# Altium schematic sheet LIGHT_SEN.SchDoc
size A4; Revision: V1.2; SheetNumber: 6; SheetTotal: 10
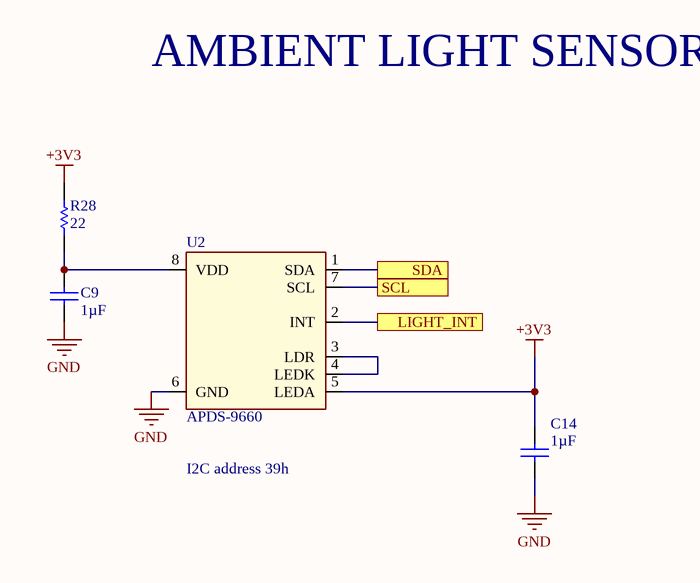
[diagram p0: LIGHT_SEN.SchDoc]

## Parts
C9  value 1µF  [CAP-0402]  (hidden comment: C0402C105K8PACTU)
C14  value 1µF  [CAP-0402]  (hidden comment: C0402C105K8PACTU)
R28  value 22  [RES-0402]  (hidden comment: RC0402FR-0722RL)
U2  APDS-9660  [APDS-9660-Footprint-1]

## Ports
LIGHT_INT, SCL, SDA

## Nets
+3V3: C14.1 R28.2 U2.5(LEDA)
GND: C9.1 C14.2 U2.6(GND)
LIGHT_INT: U2.2(INT) ; port LIGHT_INT
SCL: U2.7(SCL) ; port SCL
SDA: U2.1(SDA) ; port SDA
NetC9_2: C9.2 R28.1 U2.8(VDD)
NetU2_3: U2.3(LDR) U2.4(LEDK)

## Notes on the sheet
- AMBIENT LIGHT SENSOR
- I2C address 39h

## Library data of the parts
C9 C14 = C0017-A.11: CAP CHIP 0402 1uF 10V X5R 10%; Manufacturer: KEMET; Code Arduino: 0133
R28 = R0009-A.11: RES CHIP 0402 22R 1% 1/16W; Manufacturer: Yageo; Power: 63mW; Code Arduino: 0468
U2 = U0136-A.7: IC SENS OPT 560NM AMBIENT MODULE APDS-9960; Manufacturer: Broadcom; Code Arduino: A5475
